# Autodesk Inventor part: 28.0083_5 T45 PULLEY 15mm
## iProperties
Created: 2006-12
Document SubType Name: Modeling
Designer: Andy Moles
Material: Aluminum-6061
Part Number: 28.0083_5 T45 PULLEY 15mm
Density: 2.71 g/cm^3
Author: Andy Moles
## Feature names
1. Extrusion1
2. Extrusion3
3. Extrusion4
4. Mirror1
5. Extrusion5
6. Chamfer1
